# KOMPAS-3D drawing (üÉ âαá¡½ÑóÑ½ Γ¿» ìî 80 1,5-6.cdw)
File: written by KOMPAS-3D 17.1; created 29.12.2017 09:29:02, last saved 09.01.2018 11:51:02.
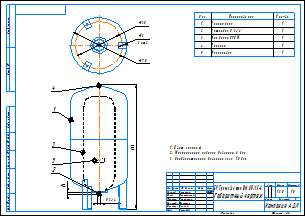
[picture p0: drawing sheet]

Sheet 1: A3, landscape, title-block layout from C:\Лощинин\GRAPHIC.LYT style 1

Title block, sheet 1: name: БР Гранлевел тип НМ 80/1,5-6 / Габаритный чертеж; mass: 13,8; sheets: 1; sheet format: A3; stored path: \\Fsk1\files\АП\20_PKO\02_Насосное направление\Разработка\04_Проекты разные\Баки\КД действующая\Баки Flexcon R\Компас\Чертежи\БР Гранлевел тип НМ 80_1,5-6.cdw; drawn by: Лощинин; checked by: Хантимеров; drawn by, date: 29.12.2017

Views: Вид 1, Спереди, Проекционный вид 2
Referenced files in \\Fsk1\files\АП\20_PKO\02_Насосное направление\Разработка\04_Проекты разные\Баки\КД действующая\Баки Flexcon R\Компас\: 80 литров.a3d
Referenced files in C:\Лощинин\: GRAPHIC.LYT
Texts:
  IvAn
  ADL
  АДЛ
  Цвет: красный
  Максимальное рабочее давление: 6 бар
  Предварительное давление газа: 1,5 бар
  ACAD_ISO03W100_RGB_223_127_255_SC_0.063_THICK_0.05
  ACAD_ISO03W100_RGB_223_127_255_SC_1_THICK_0.05
  Лит-Масса-Масштаб
  Материал-Предприятие
  Масштаб
  Изм.
  Лист
  № докум.
  Подп.
  Дата
  Лит.
  Разраб.
  Пров.
  Т.контр.
  Курлыкина
  Листов
  Нач.отд.
  Щетинин
  Н.контр.
  Долгов
  Утв.
  Рашидов
  Компания АДЛ
  Изменение
  Номер документа
  Подпись
  Обозначение документа
  Наименование изделия
  Масса изделия по ГОСТ 2.109-73
  Порядковый номер листа
  Общее количество листов в документе
  Характер работы, выполненной лицом, подписавшим документ
  Наименование или индекс предприятия, выпускающего документ
  Инв. № подл.
  Подп. и дата
  Взам. инв. №
  Инв. № дубл.
  Инвентарный номер подлинника по ГОСТ 2.501-68
  Подпись принявшего подлинник в отдел технической документации
  Инвентарный номер подлинника, взамен которого выпущен данный подлинник
  Инвентарный номер дубликата по ГОСТ 2.502-68
  Подпись принявшего дубликат в отдел технической документации
  Справ. №
  Перв. примен.
  Обозначение документа, взамен или на основании которого выпущен данный документ
  Обозначение документа, в котором впервые записан данный документ
  Подпись лица, копировавшего чертеж
  Обозначение формата листа
Dimensions and other numbers on the sheet: 864; 16; 2; 5; 3; 4; 1; 330; 390; 13; 3 отв.; 1:5; 13,8; 29.12.2017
